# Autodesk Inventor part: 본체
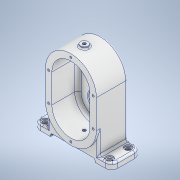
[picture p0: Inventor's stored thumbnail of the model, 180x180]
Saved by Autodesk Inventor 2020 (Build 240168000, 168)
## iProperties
Created: 2021-05
Part Number: 본체
Material: 알루미늄 6061
Document SubType Name: Modeling
Designer: Owner
Density: 2.7 g/cm^3
Appearance: 알루미늄 - 평지
Mass: 758.409 g
Surface Area: 590.625 cm^2
Volume: 280.892 cm^3
Author: Owner
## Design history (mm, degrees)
sketch "스케치1"
  geometry: L1 (0, 22.5)-(0, -22.5); L2 (-40, 22.5)-(-40, -22.5); L3 (40, -22.5)-(40, 22.5); A1 r 40 centre (0, 22.5) between (40, 22.5) and (-40, 22.5); A2 r 40 centre (0, -22.5) between (-40, -22.5) and (40, -22.5); 2 further points
  constraints: 8 end point, 4 point on circle, 4 tangent, 2 centre point, 1 coincident, 1 midpoint, 1 parallel, 1 vertical
  dimensions: "d0" = 80 distance between parallel lines of L3 L2; "d1" = 45 distance of L1.end L1.start
extrude "돌출1" new body sketch "스케치1" stored distance "d2" = 49; taper "d3" = 0 deg
sketch "스케치3"
  geometry: L1 (0, 22.5)-(0, -22.5); L2 (30, 22.5)-(30, -22.5); L3 (-30, -22.5)-(-30, 22.5); A1 r 30 centre (0, 22.5) between (30, 22.5) and (-30, 22.5); A2 r 30 centre (0, -22.5) between (-30, -22.5) and (30, -22.5); 2 further points
  constraints: 8 end point, 4 point on circle, 4 tangent, 2 centre point, 1 coincident, 1 midpoint, 1 parallel, 1 vertical
  dimensions: "d7" = 60 distance between parallel lines of L2 L3; "d8" = 45 distance of L1.end L1.start
extrude "돌출2" cut sketch "스케치3" distance "d9" = 41; taper "d10" = 0 deg
fillet "모깎기1" dims "d11" = 5
sketch "스케치5"
  geometry: L1 (0, 22.5)-(0, -22.5); L2 (-26, 22.5)-(-26, -22.5); L3 (26, -22.5)-(26, 22.5); A1 r 26 centre (0, 22.5) between (26, 22.5) and (-26, 22.5); A2 r 26 centre (0, -22.5) between (-26, -22.5) and (26, -22.5); 2 further points
  constraints: 8 end point, 4 point on circle, 4 tangent, 2 centre point, 1 coincident, 1 midpoint, 1 parallel, 1 vertical
  dimensions: "d18" = 52 distance between parallel lines of L3 L2; "d19" = 45 distance of L1.end L1.start
extrude "돌출4" join sketch "스케치5" distance "d20" = 8; taper "d21" = 0 deg
sketch "스케치6"
  geometry: L1 (-26, -7.5)-(-26, -22.5); L2 (26, -22.5)-(26, -7.5); L3 (-26, -7.5)-(26, -7.5); L4 (0, 22.5)-(0, -7.5); A1 r 26 centre (0, 22.5) between (26, 22.5) and (-26, 22.5) reference; A2 r 26 centre (0, -22.5) between (-26, -22.5) and (26, -22.5); 2 further points
  constraints: 8 end point, 2 midpoint, 2 point on circle, 2 tangent, 2 vertical, 1 centre point, 1 horizontal, 1 parallel
  dimensions: "d22" = 52 distance of L1.start L2.end; "d23" = 30 distance of L4.end L4.start; "d24" = 41 dimension on A2 L3
extrude "돌출5" join sketch "스케치6" distance "d25" = 3; taper "d26" = 0 deg
fillet "모깎기2" dims "d27" = 3
sketch "스케치7"
  geometry: L1 (0, 0)-(0, 22.5); L2 (0, 0)-(0, -22.5); C1 r 14 at (0, 22.5); C2 r 14 at (0, -22.5)
  constraints: 4 end point, 2 centre point, 2 coincident, 2 vertical
  dimensions: "d28" = 22.5 distance of L1.start L1.end; "d29" = 22.5 distance of L1.start L2.end; "d30" = 28 diameter of C1; "d31" = 28 diameter of C2
extrude "돌출6" cut sketch "스케치7" distance "d32" = 8; taper "d33" = 0 deg
sketch "스케치9"
  geometry: L1 (-25, -45)-(-25, 0) reference; L2 (25, 0)-(25, -45) reference; C1 r 14 at (0, -45) reference; C2 r 14 at (0, 0) reference; C3 r 11 at (0, 0); A1 r 25 centre (0, -45) between (-25, -45) and (25, -45) reference; A2 r 25 centre (0, 0) between (25, 0) and (-25, 0) reference; 1 further point
  constraints: 1 centre point, 1 coincident
  dimensions: "d38" = 22 diameter of C3
extrude "돌출8" cut sketch "스케치9" distance "d39" = 4; taper "d40" = 0 deg
sketch "스케치10"
  geometry: L1 (-25, -45)-(-25, 0) reference; L2 (25, 0)-(25, -45) reference; C1 r 14 at (0, -45) reference; C2 r 14 at (0, 0) reference; C3 r 14 at (0, 0); A1 r 25 centre (0, -45) between (-25, -45) and (25, -45) reference; A2 r 25 centre (0, 0) between (25, 0) and (-25, 0) reference; 1 further point
  constraints: 1 centre point, 1 coincident
  dimensions: "d41" = 28 diameter of C3
extrude "돌출9" cut sketch "스케치10" distance "d42" = 4; taper "d43" = 0 deg
chamfer "모따기1" distance "d44" = 1; stored, may be unused: second distance "d45" = 2, angle "d46" = 45 deg
fillet "모깎기3" dims "d47" = 0.3
chamfer "모따기2" distance "d48" = 1; stored, may be unused: second distance "d49" = 2, angle "d50" = 45 deg
sketch "스케치12"
  geometry: L1 (26, 15)-(-26, 15) reference; L2 (-25, 0)-(-25, 45) reference; L3 (25, 45)-(25, 0) reference; C1 r 15 at (0, 45) reference; C2 r 15 at (0, 0) reference; C3 r 10 at (0, 0); A1 r 25 centre (0, 0) between (-25, 0) and (25, 0) reference; A2 r 25 centre (0, 45) between (25, 45) and (-25, 45) reference; 1 further point
  constraints: 1 centre point, 1 coincident
  dimensions: "d51" = 20 diameter of C3
extrude "돌출10" cut sketch "스케치12" distance "d52" = 4; taper "d53" = 0 deg
fillet "모깎기4" dims "d54" = 3
sketch "스케치14"
  geometry: C1 r 11 at (0, 22.5) reference; C2 r 10 at (0, -22.5) reference; A1 r 35 centre (0, 22.5) between (35, 22.5) and (-35, 22.5); 4 further points
  constraints: 3 coincident, 3 point on circle, 1 centre point
  dimensions: "d57" = 35 radius of A1
hole "구멍1" sketch "스케치14" at (-35, 22.5), (0, 57.5), (35, 22.5) diameter "d58" = 3.242; stored, may be unused: countersink angle "d62" = 90 deg, drill point angle "d64" = 118 deg; dims "d59" = 8, "d60" = 4, "d61" = 2, "d63" = 10
sketch "스케치15"
  geometry: L1 (0, 22.5)-(0, 42.5); 1 further point
  constraints: 2 end point, 1 vertical
  dimensions: "d67" = 20 distance of L1.start L1.end
hole "구멍2" sketch "스케치15" at (0, 42.5) diameter "d68" = 3.242; stored, may be unused: countersink angle "d72" = 90 deg, drill point angle "d74" = 118 deg; dims "d69" = 8, "d70" = 4, "d71" = 2, "d73" = 10
node "작업 평면2"
sketch "스케치17"
  geometry: L1 (35, -69.5)-(61, -69.5); L2 (61, -69.5)-(61, -59.5); L3 (40, 22.5)-(40, -22.5) reference; L4 (40, -22.5)-(40, -59.5); L5 (40, -59.5)-(61, -59.5); L6 (-40, -22.5)-(-40, -59.5); L7 (-40, -59.5)-(-61, -59.5); L8 (-61, -69.5)-(-61, -59.5); L9 (-35, -69.5)-(-61, -69.5); L10 (35, -64.5)-(-35, -64.5); L11 (-35, -64.5)-(-35, -69.5); L12 (35, -69.5)-(35, -64.5); A1 r 40 centre (0, -22.5) between (-40, -22.5) and (40, -22.5) reference; 2 further points
  constraints: 22 end point, 3 horizontal, 3 perpendicular, 3 vertical, 1 parallel
  dimensions: "d90" = 122 distance between parallel lines of L8 L2; "d91" = 70 distance of L10.start L10.end; "d92" = 5 distance from line of L1 L10.start; "d93" = 10 distance between parallel lines of L1 L5
extrude "돌출12" join sketch "스케치17" distance "d94" = 46; taper "d95" = 0 deg
fillet "모깎기5" dims "d96" = 10
sketch "스케치18"
  geometry: 3 further points
  constraints: 1 coincident
hole "구멍3" sketch "스케치18" at (-11, 36) diameter "d97" = 6.6; stored, may be unused: countersink angle "d101" = 90 deg, drill point angle "d103" = 0 deg; dims "d98" = 8, "d99" = 11, "d100" = 2, "d102" = 10
node "작업 평면3"
sketch "스케치19"
  geometry: L1 (5, 49)-(-75, 49) reference; L2 (-65, 49)-(-5, 49) reference; L3 (-35, 49)-(-35, 28); C1 r 6 at (-35, 28)
  constraints: 2 end point, 1 centre point, 1 coincident, 1 midpoint, 1 vertical
  dimensions: "d136" = 21 distance of L3.start L3.end; "d137" = 12 diameter of C1
extrude "돌출13" join sketch "스케치19" stored distance "d106" = 46; taper "d107" = 0 deg
fillet "모깎기6" dims "d138" = 2
hole "구멍4" sketch "스케치19" diameter "d109" = 4.917; stored, may be unused: countersink angle "d113" = 90 deg, drill point angle "d115" = 0 deg; dims "d110" = 12, "d111" = 11, "d112" = 2, "d114" = 17.1
sketch "스케치20"
  geometry: L1 (75, 3)-(-5, 3) reference; L2 (5, 3)-(65, 3) reference; L3 (35, 3)-(35, -18); 2 further points
  constraints: 2 end point, 1 coincident, 1 midpoint, 1 vertical
  dimensions: "d116" = 21 distance of L3.start L3.end
hole "구멍5" sketch "스케치20" diameter "d117" = 12; stored, may be unused: countersink angle "d121" = 90 deg, drill point angle "d123" = 0 deg; dims "d118" = 12, "d119" = 11, "d120" = 2, "d122" = 1
hole "구멍6" sketch "스케치20" diameter "d124" = 4.917; stored, may be unused: countersink angle "d128" = 90 deg, drill point angle "d130" = 0 deg; dims "d125" = 12, "d126" = 11, "d127" = 2, "d129" = 17.1
sketch "스케치22"
  geometry: L1 (-61, -57.5)-(61.113, -57.5); L2 (-51, -69.5)-(-35, -69.5) reference; 2 further points
  constraints: 2 end point, 2 horizontal, 1 midpoint
  dimensions: "d133" = 12 distance between parallel lines of L2 L1
feature "엠보싱1" sketch "스케치22" dims "d134" = 0.5, "d135" = 0
fillet "모깎기7" dims "d139" = 3
fillet "모깎기8" dims "d140" = 3
fillet "모깎기9" dims "d141" = 3
fillet "모깎기10" dims "d142" = 3
node "솔리드1"
mirror "미러1"
pattern_circular "원형 패턴1" dims angle "d76" = 360 deg
mirror "미러2"
mirror "미러3"
node "투영된 루프2"
node "투영된 루프3"
node "투영된 루프4"
feature "A9D066F2-1C7D-4E18-AEED-F7BC21143FA4" dims "d97" = 6.6, "d98" = 8, "d99" = 11, "d100" = 2, "d101" = 90 deg, "d102" = 10, "d103" = 0
other parameters: "d84" = -46, "d104" = -135
